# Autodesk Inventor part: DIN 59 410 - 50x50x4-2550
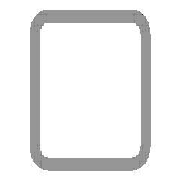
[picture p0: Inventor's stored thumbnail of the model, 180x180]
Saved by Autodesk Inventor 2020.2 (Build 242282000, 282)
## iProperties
Manager: www.cadconsulting.pl
Company: Fabian Stasiak CAD Consulting
IsCustomPart: 1
_CCFamilyMember: 40
_CCFamilyDisplayName: DIN 59410 (Kwadrat) - Rurki stalowe o przekroju kwadratowym formowane na gorąco
_FrameMemberDoc: Frame Member File
_Version: 15.0.0
_GetPNFromCC: 1
Created: 2015-01
Part Number: DIN 59 410 - 50x50x4-2550
Material: Stal, miękka
Description: Rurki stalowe o przekroju kwadratowym formowane na gorąco
Document SubType Name: Modellieren
Standard: DIN
Designer: F.Stasiak
Standards Organization: DIN
Language: pl-PL
Size Designation: 50x50x4
Categories: <MemberInstance><Categories><Category DisplayName="Kształtowniki konstrukcyjne" InternalName="089c4875-fa83-4c05-b084-43b9cc11f5ed" Mnemonic="GRDR"><CategoryPar
Stock Number: 50x50x4
Density: 7.85 g/cm^3
Appearance: Częściowo polerowana
Mass: 13635.4 g
Surface Area: 8704.61 cm^2
Volume: 1736.99 cm^3
Catalog Web Link: www.expertbooks.pl
G_L: 2550,000 mm
G_W: 50,000 mm
G_H: 50,000 mm
+D23F4B60-F1AB-4C70-B588-4AD65F3BC300+CUTDETAIL1: Połączenie narożnikowe 45,00 deg
+2A0B5DE6-791F-402A-8B32-3269641191C7+CUTDETAIL2: Połączenie narożnikowe 45,00 deg
Author: F.Stasiak
Subject: Zbiór ćwiczeń. Autodesk Inventor 2020. Kurs Professional
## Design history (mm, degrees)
node "Płaszczyzna początkowa"
node "Płaszczyzna końcowa"
sketch "Szkic1"
  geometry: L1 (-17, 25)-(17, 25); L2 (25, 17)-(25, -17); L3 (17, -25)-(-17, -25); L4 (-25, -17)-(-25, 17); L5 (-36.682, 0)-(36.682, 0) reference; L6 (0, -36.682)-(0, 36.682) reference; L7 (-17, 21)-(17, 21); L8 (21, 17)-(21, -17); L9 (17, -21)-(-17, -21); L10 (-21, -17)-(-21, 17); A1 r 8 centre (-17, 17) between (-17, 25) and (-25, 17); A2 r 8 centre (17, 17) between (25, 17) and (17, 25); A3 r 8 centre (17, -17) between (17, -25) and (25, -17); A4 r 8 centre (-17, -17) between (-25, -17) and (-17, -25); A5 r 4 centre (-17, 17) between (-17, 21) and (-21, 17); A6 r 4 centre (17, 17) between (21, 17) and (17, 21); A7 r 4 centre (17, -17) between (17, -21) and (21, -17); A8 r 4 centre (-17, -17) between (-21, -17) and (-17, -21); 3 further points
  constraints: 16 end point, 16 point on circle, 8 centre point, 8 tangent, 6 point on line, 4 parallel, 3 equal radius, 3 perpendicular, 1 horizontal, 7 other
  dimensions: "b" = 50 distance of point (-25, 25) point (25, 25); "msp_r" = 8 radius of A1 (= 2 x ParT); "d8" = 25 distance between parallel lines of L4 L6 (= d9); "d9" = 25 distance between parallel lines of L3 L5 (= 0.5 x b); "d10" = 4 distance between parallel lines of L3 L9 (= ParT)
extrude "Bryła" new body sketch "Szkic1" taper "d4" = 0 deg; stored distance "NLG" = 10
node "Driven Length"
  sketch "Sketch2"
    geometry: L1 (0, 0)-(10, 0) reference
    constraints: 2 end point, 1 horizontal
  workplane "Work Plane3"
  sketch "Sketch3"
    geometry: L1 (-2, -25)-(12, -25) reference; L2 (-2, 2525)-(12, 2525) reference
    dimensions: "d14" = 2550 distance between parallel lines of L1 L2 (derived)
node "Płaszczyzna konstrukcyjna4"
feature "Podział1"
node "Płaszczyzna konstrukcyjna5"
feature "Podział2"
body "Solid1"
other parameters: "ParT" = 4, "G_OFFSET_START" = 25 [user parameter; used in 1 equation term], "G_OFFSET_END" = 25 [user parameter; used in 1 equation term], "d11" = -25 (= -G_OFFSET_START), "d12" = 2525 (= G_OFFSET_END + B_L), "G_L" = 2550 (= d14) [user parameter], "d13" = 90 deg
